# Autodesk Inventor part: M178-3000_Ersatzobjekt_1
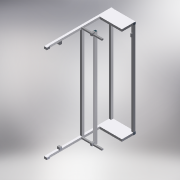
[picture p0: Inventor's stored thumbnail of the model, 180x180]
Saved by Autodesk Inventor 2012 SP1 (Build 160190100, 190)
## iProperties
Created: 2012-04
Part Number: M178-3000_Ersatzobjekt_1
Material: 1.0038 St 37-2K
Document SubType Name: Modeling
Designer: jwagner
Density: 7.85 g/cm^3
RuleStatus: InUse
AfterMaterialChange0: Fx.Material.Update
AfterAnyiPropertyChange0: iProp.Update
AfterAnyiPropertyChange1: Fx.Material.Update
Author: jwagner
Revision Number: A
ABMESSUNG_HZ: 100x100x10
BESCHREIBUNG: <freier Text>
EV_KENNUNG: <keine>
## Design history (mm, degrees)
derived "M178-3000.iam"
node "Volumenkörper3"
feature "尀볐"
node "M178-3001.ipt:1"
node "M178-3001.ipt:2"
node "21-135 Corner Phantom.iam:1"
sketch "22-130.iam:1"
sketch "22-134.iam:1"
sketch "22-130.iam:2"
sketch "22-134.iam:2"
sketch "21-135 Corner Phantom.iam:2"
node "M178-3002.ipt:3"
node "21-135 Corner Phantom 2.iam:1"
node "21-135 Corner Phantom 2.iam:2"
sketch "M178-100_Cross_Phantom.iam:1"
sketch "M178-100_Cross_Phantom.iam:2"
sketch "M178-100_Cross_Phantom.iam:3"
sketch "22-136.ipt:1"
sketch "18-813.ipt:5"
sketch "18-813.ipt:6"
sketch "M178-3000 Overhange Phantom.iam:1"
sketch "18-813.ipt:1"
sketch "18-813.ipt:2"
sketch "M178-3000 Overhange Phantom.iam:2"
sketch "18-813.ipt:7"
sketch "18-813.ipt:8"
node "M178-3000.iam_Körper"
other parameters: "Length" = 1748.8, "Length_1" = 1748.8, "Length_2" = 1748.8, "Length_3" = 417.2, "Length_4" = 304.8, "Length_5" = 417.2, "Length_6" = 304.8, "Length_7" = 1219.2, "Length_8" = 1219.2, "Length_9" = 1828.8
